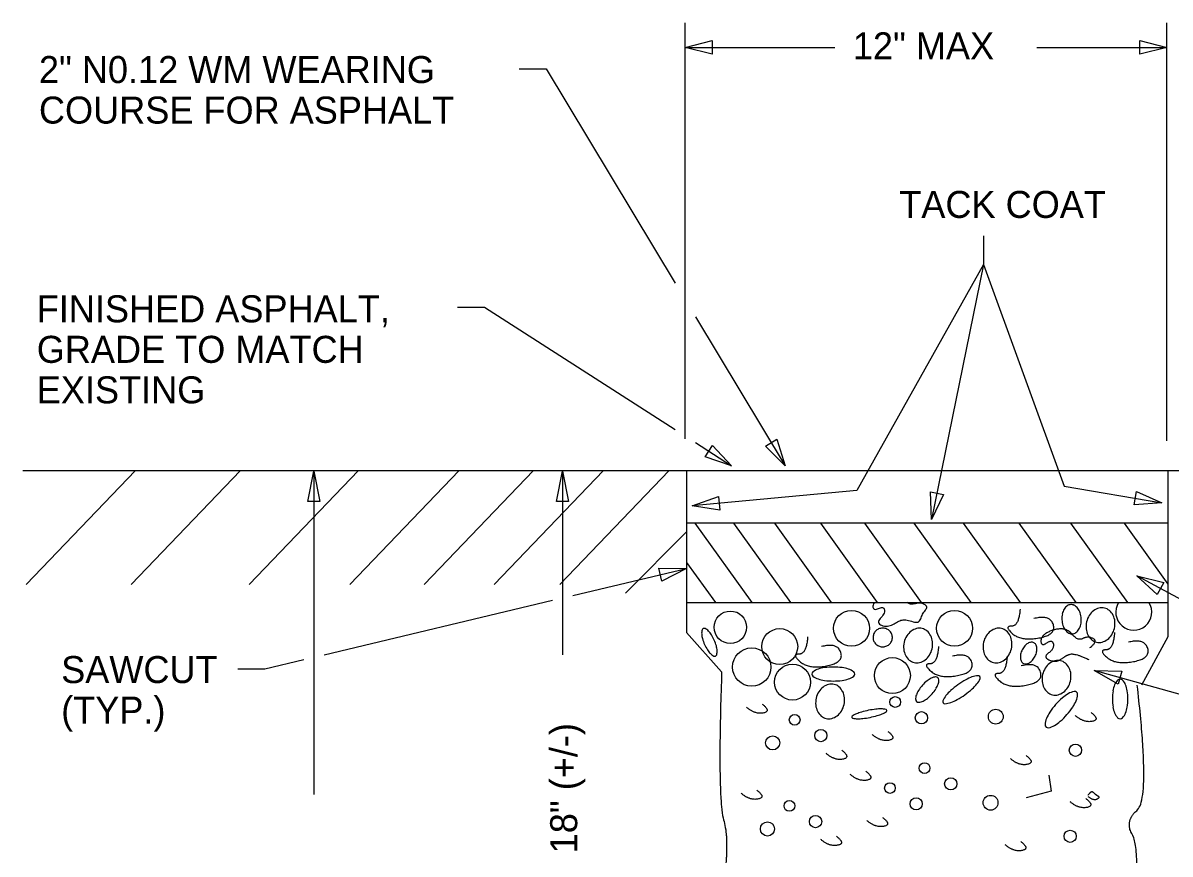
# Model space of a CAD drawing. Extents: x 10310.4 to 10401.1, y 10100.5 to 10143.6.
# Drawn here: x 10310.38 to 10338.7, y 10122.98 to 10143.48 of the extents above; entities that cross this region are included whole.
import ezdxf

# ---------------------------------------------------------------- set-up
doc = ezdxf.new("R2010")
doc.units = 0
for name, color, linetype in [('G-ANNO-TEXT', 7, 'Continuous'), ('G-DETL-LINE', 7, 'Continuous'), ('G-DETL-PATT', 7, 'Continuous')]:
    doc.layers.add(name, color=color, linetype=linetype)

msp = doc.modelspace()

# ---------------------------------------------------------------- linework, layer by layer
at = {"layer": 'G-ANNO-TEXT'}
for p, q in [((10326.732, 10133.217), (10326.732, 10143.483)), ((10338.624, 10133.174), (10338.624, 10143.483)), ((10326.732, 10142.88), (10330.423, 10142.88)), ((10335.408, 10142.88), (10338.624, 10142.88)), ((10322.63, 10142.355), (10323.297, 10142.355)), ((10323.297, 10142.355), (10326.482, 10137.063)), ((10334.093, 10137.519), (10332.813, 10131.227)), ((10321.107, 10136.471), (10321.774, 10136.471)), ((10321.774, 10136.471), (10326.482, 10133.448)), ((10326.982, 10136.232), (10329.195, 10132.554)), ((10326.982, 10133.127), (10327.873, 10132.554)), ((10317.561, 10132.423), (10317.561, 10124.448)), ((10323.701, 10132.426), (10323.701, 10127.888)), ((10323.951, 10129.355), (10326.765, 10130.024)), ((10341.376, 10127.947), (10337.879, 10129.844)), ((10317.811, 10127.895), (10323.451, 10129.236)), ((10315.684, 10127.548), (10316.35, 10127.548)), ((10316.35, 10127.548), (10317.311, 10127.776)), ((10341.293, 10126.261), (10336.825, 10127.508))]:
    msp.add_line(p, q, dxfattribs=at)
for points in [[(10327.398, 10142.714), (10326.732, 10142.88), (10327.398, 10143.047)], [(10337.957, 10143.047), (10338.624, 10142.88), (10337.957, 10142.714)], [(10328.994, 10133.212), (10329.195, 10132.554), (10328.709, 10133.04)], [(10327.402, 10133.055), (10327.873, 10132.554), (10327.222, 10132.774)], [(10317.411, 10131.673), (10317.561, 10132.423), (10317.711, 10131.673)], [(10323.551, 10131.676), (10323.701, 10132.426), (10323.851, 10131.676)], [(10327.582, 10131.462), (10326.903, 10131.567), (10327.551, 10131.794)], [(10333.11, 10131.848), (10332.813, 10131.227), (10332.783, 10131.914)], [(10337.869, 10131.919), (10338.498, 10131.642), (10337.813, 10131.591)], [(10326.078, 10130.032), (10326.765, 10130.024), (10326.155, 10129.708)], [(10338.385, 10129.38), (10337.879, 10129.844), (10338.544, 10129.673)], [(10337.422, 10127.169), (10336.825, 10127.508), (10337.512, 10127.49)]]:
    msp.add_lwpolyline(points, close=True, dxfattribs=at)
for points in [[(10334.093, 10138.234), (10334.093, 10137.519), (10330.969, 10131.943), (10326.903, 10131.567)], [(10334.093, 10137.519), (10336.089, 10132.056), (10338.498, 10131.642)]]:
    msp.add_lwpolyline(points, dxfattribs=at)
at = {"layer": 'G-DETL-LINE'}
for p, q in [((10310.377, 10132.442), (10354.529, 10132.442)), ((10326.765, 10132.442), (10326.765, 10131.144)), ((10338.647, 10132.442), (10338.647, 10129.182)), ((10326.765, 10131.144), (10326.757, 10129.182)), ((10338.647, 10131.144), (10326.757, 10131.144)), ((10326.757, 10129.182), (10338.647, 10129.182)), ((10326.765, 10129.182), (10326.765, 10128.442)), ((10338.647, 10129.182), (10338.647, 10128.334)), ((10326.765, 10128.442), (10327.629, 10127.469)), ((10338.647, 10128.334), (10337.999, 10127.143))]:
    msp.add_line(p, q, dxfattribs=at)
msp.add_open_spline([(10327.629, 10127.469), (10327.521, 10124.332), (10327.845, 10123.251), (10327.413, 10120.548), (10328.061, 10118.17), (10327.953, 10116.764), (10328.493, 10115.899), (10327.737, 10114.386), (10328.277, 10110.818), (10331.41, 10111.359), (10333.786, 10110.385), (10335.622, 10111.359), (10337.135, 10111.683), (10337.999, 10113.845), (10337.459, 10118.278), (10337.999, 10123.035), (10337.567, 10123.792), (10338.215, 10124.332), (10337.891, 10127.143)], degree=2, dxfattribs=at)
at = {"layer": 'G-DETL-PATT'}
for p, q in [((10313.155, 10132.441), (10310.454, 10129.63)), ((10315.747, 10132.441), (10313.046, 10129.63)), ((10318.663, 10132.441), (10315.963, 10129.63)), ((10321.148, 10132.441), (10318.447, 10129.63)), ((10322.984, 10132.441), (10320.284, 10129.63)), ((10324.712, 10132.441), (10322.012, 10129.63)), ((10326.333, 10132.441), (10323.632, 10129.63)), ((10326.969, 10131.144), (10328.373, 10129.182)), ((10327.923, 10131.144), (10329.327, 10129.182)), ((10328.93, 10131.144), (10330.334, 10129.182)), ((10330.069, 10131.144), (10331.473, 10129.182)), ((10331.155, 10131.144), (10332.559, 10129.182)), ((10332.374, 10131.144), (10333.778, 10129.182)), ((10333.593, 10131.144), (10334.997, 10129.182)), ((10334.97, 10131.144), (10336.374, 10129.182)), ((10336.242, 10131.144), (10337.646, 10129.182)), ((10337.567, 10131.144), (10338.647, 10129.634)), ((10326.765, 10130.927), (10325.253, 10129.414)), ((10326.765, 10130.171), (10327.473, 10129.182)), ((10335.709, 10124.921), (10335.765, 10124.527)), ((10335.765, 10124.527), (10335.147, 10124.359))]:
    msp.add_line(p, q, dxfattribs=at)
for points in [[(10331.4, 10129.182), (10331.394, 10129.173), (10331.38, 10129.146), (10331.37, 10129.119), (10331.366, 10129.094), (10331.366, 10129.07), (10331.37, 10129.049), (10331.378, 10129.032), (10331.391, 10129.02), (10331.407, 10129.014), (10331.427, 10129.013), (10331.45, 10129.018), (10331.474, 10129.026), (10331.5, 10129.036), (10331.526, 10129.045), (10331.552, 10129.053), (10331.575, 10129.058), (10331.597, 10129.058), (10331.615, 10129.051), (10331.63, 10129.039), (10331.64, 10129.022), (10331.647, 10129.001), (10331.649, 10128.977), (10331.647, 10128.95), (10331.64, 10128.922), (10331.628, 10128.894), (10331.61, 10128.866), (10331.59, 10128.839), (10331.567, 10128.812), (10331.545, 10128.786), (10331.526, 10128.761), (10331.51, 10128.736), (10331.501, 10128.713), (10331.5, 10128.691), (10331.508, 10128.67), (10331.524, 10128.651), (10331.548, 10128.634), (10331.577, 10128.62), (10331.61, 10128.608), (10331.646, 10128.601), (10331.683, 10128.597), (10331.72, 10128.598), (10331.756, 10128.604), (10331.79, 10128.613), (10331.823, 10128.626), (10331.855, 10128.642), (10331.885, 10128.658), (10331.915, 10128.676), (10331.944, 10128.693), (10331.972, 10128.709), (10332, 10128.722), (10332.028, 10128.734), (10332.056, 10128.743), (10332.085, 10128.75), (10332.114, 10128.754), (10332.145, 10128.755), (10332.177, 10128.753), (10332.211, 10128.748), (10332.246, 10128.74), (10332.283, 10128.73), (10332.32, 10128.719), (10332.357, 10128.709), (10332.392, 10128.701), (10332.425, 10128.695), (10332.454, 10128.695), (10332.48, 10128.7), (10332.501, 10128.711), (10332.518, 10128.729), (10332.532, 10128.751), (10332.543, 10128.777), (10332.554, 10128.805), (10332.565, 10128.835), (10332.577, 10128.865), (10332.59, 10128.894), (10332.606, 10128.921), (10332.624, 10128.947), (10332.642, 10128.97), (10332.659, 10128.993), (10332.674, 10129.014), (10332.685, 10129.033), (10332.692, 10129.053), (10332.692, 10129.071)], [(10332.692, 10129.071), (10332.685, 10129.089), (10332.672, 10129.106), (10332.653, 10129.122), (10332.63, 10129.136), (10332.603, 10129.147), (10332.573, 10129.156), (10332.542, 10129.162), (10332.511, 10129.164), (10332.48, 10129.162), (10332.449, 10129.157), (10332.418, 10129.152), (10332.387, 10129.146), (10332.357, 10129.141), (10332.326, 10129.14), (10332.295, 10129.142), (10332.264, 10129.151), (10332.232, 10129.166), (10332.206, 10129.182)]]:
    msp.add_lwpolyline(points, dxfattribs=at)
for centre, radius in [((10327.844, 10128.571), 0.401), ((10330.837, 10128.545), 0.444), ((10333.381, 10128.545), 0.444), ((10329.062, 10128.094), 0.444), ((10328.373, 10127.59), 0.474), ((10329.38, 10127.219), 0.444), ((10331.844, 10127.378), 0.444), ((10331.915, 10126.727), 0.132), ((10329.432, 10126.287), 0.132), ((10332.561, 10126.339), 0.151), ((10334.398, 10126.365), 0.183), ((10328.889, 10125.718), 0.174), ((10330.078, 10125.899), 0.151), ((10336.364, 10125.536), 0.151), ((10332.639, 10125.096), 0.132), ((10331.785, 10124.604), 0.132), ((10333.286, 10124.708), 0.151), ((10329.302, 10124.163), 0.132), ((10332.432, 10124.215), 0.151), ((10334.268, 10124.241), 0.183), ((10329.948, 10123.775), 0.151), ((10328.759, 10123.594), 0.174), ((10336.234, 10123.413), 0.151)]:
    msp.add_circle(centre, radius, dxfattribs=at)
for centre, radius, start, end in [((10336.422, 10128.821), 0.39, 149.7707, 167.9003), ((10336.323, 10128.878), 0.275, 125.3075, 149.7707), ((10336.257, 10128.971), 0.161, 93.1837, 125.3075), ((10336.257, 10128.971), 0.161, 61.0599, 93.1837), ((10336.202, 10128.872), 0.275, 36.5967, 61.0599), ((10336.11, 10128.803), 0.39, 18.4671, 36.5967), ((10337.076, 10128.633), 0.436, 127.6669, 148.2475), ((10337.033, 10128.687), 0.367, 103.8137, 127.6669), ((10337.015, 10128.761), 0.292, 76.9901, 103.8137), ((10337.015, 10128.761), 0.292, 50.1666, 76.9901), ((10336.967, 10128.703), 0.367, 26.3134, 50.1666), ((10337.805, 10128.943), 0.444, 147.4871, 32.5129), ((10336.576, 10128.788), 0.547, 167.9002, 183.1837), ((10336.576, 10128.788), 0.547, 183.1837, 198.4671), ((10335.961, 10128.753), 0.547, 3.1837, 18.4671), ((10335.961, 10128.753), 0.547, 347.9003, 3.1837), ((10337.151, 10128.586), 0.525, 166.9901, 185.7327), ((10337.151, 10128.586), 0.525, 148.2475, 166.9901), ((10336.905, 10128.672), 0.436, 5.7327, 26.3134), ((10336.816, 10128.663), 0.525, 346.9901, 5.7327), ((10327.42, 10128.425), 0.285, 163.6744, 184.6242), ((10327.724, 10128.45), 0.59, 184.6242, 195.7056), ((10327.198, 10128.491), 0.0534, 113.9883, 163.6744), ((10327.198, 10128.491), 0.0534, 64.3023, 113.9883), ((10327.097, 10128.282), 0.285, 43.3524, 64.3023), ((10326.876, 10128.073), 0.59, 32.271, 43.3524), ((10331.591, 10128.32), 0.224, 153.6698, 176.8163), ((10331.598, 10128.317), 0.232, 130.9122, 153.6698), ((10331.602, 10128.312), 0.238, 108.684, 130.9122), ((10331.605, 10128.305), 0.246, 86.8163, 108.684), ((10331.605, 10128.305), 0.246, 64.9486, 86.8163), ((10331.608, 10128.312), 0.238, 42.7204, 64.9486), ((10331.613, 10128.316), 0.232, 19.9629, 42.7204), ((10331.62, 10128.319), 0.224, 356.8163, 19.9629), ((10332.572, 10128.129), 0.436, 127.6669, 148.2475), ((10332.53, 10128.183), 0.367, 103.8137, 127.6669), ((10332.511, 10128.257), 0.292, 76.9901, 103.8137), ((10332.511, 10128.257), 0.292, 50.1666, 76.9901), ((10332.463, 10128.199), 0.367, 26.3134, 50.1666), ((10334.532, 10128.129), 0.436, 127.6669, 148.2475), ((10334.49, 10128.183), 0.367, 103.8137, 127.6669), ((10334.472, 10128.257), 0.292, 76.9901, 103.8137), ((10334.472, 10128.257), 0.292, 50.1666, 76.9901), ((10334.423, 10128.199), 0.367, 26.3134, 50.1666), ((10336.427, 10128.738), 0.39, 198.4671, 216.5967), ((10336.335, 10128.669), 0.275, 216.5967, 241.0599), ((10336.28, 10128.57), 0.161, 241.0599, 273.1837), ((10336.28, 10128.57), 0.161, 273.1837, 305.3075), ((10336.214, 10128.663), 0.275, 305.3075, 329.7707), ((10336.115, 10128.72), 0.39, 329.7707, 347.9003), ((10337.063, 10128.577), 0.436, 185.7327, 206.3134), ((10336.816, 10128.663), 0.525, 328.2475, 346.9901), ((10328.171, 10128.576), 1.055, 195.7056, 203.9883), ((10328.171, 10128.576), 1.055, 203.9883, 212.271), ((10326.483, 10127.824), 1.055, 23.9883, 32.271), ((10326.483, 10127.824), 1.055, 15.7056, 23.9883), ((10326.93, 10127.95), 0.59, 4.6242, 15.7056), ((10331.591, 10128.32), 0.224, 176.8163, 199.9629), ((10331.598, 10128.323), 0.232, 199.9629, 222.7204), ((10331.603, 10128.327), 0.238, 222.7204, 244.9486), ((10331.606, 10128.334), 0.246, 244.9486, 266.8163), ((10331.609, 10128.327), 0.238, 288.684, 310.9122), ((10331.613, 10128.322), 0.232, 310.9122, 333.6698), ((10331.62, 10128.319), 0.224, 333.6698, 356.8163), ((10332.647, 10128.082), 0.525, 166.9901, 185.7327), ((10332.647, 10128.082), 0.525, 148.2475, 166.9901), ((10332.401, 10128.168), 0.436, 5.7327, 26.3134), ((10332.313, 10128.159), 0.525, 346.9901, 5.7327), ((10334.608, 10128.082), 0.525, 166.9901, 185.7327), ((10334.608, 10128.082), 0.525, 148.2475, 166.9901), ((10334.361, 10128.168), 0.436, 5.7327, 26.3134), ((10334.273, 10128.159), 0.525, 346.9901, 5.7327), ((10335.462, 10127.808), 0.461, 139.002, 153.4071), ((10335.353, 10127.903), 0.317, 121.6044, 139.002), ((10335.299, 10127.991), 0.213, 97.1495, 121.6044), ((10335.286, 10128.09), 0.113, 63.4071, 97.1495), ((10335.286, 10128.09), 0.113, 29.6647, 63.4071), ((10335.2, 10128.041), 0.213, 5.2099, 29.6647), ((10337.001, 10128.546), 0.367, 206.3134, 230.1666), ((10336.952, 10128.488), 0.292, 230.1666, 256.9901), ((10336.952, 10128.488), 0.292, 256.9901, 283.8137), ((10336.934, 10128.562), 0.367, 283.8137, 307.6669), ((10336.892, 10128.616), 0.436, 307.6669, 328.2475), ((10327.778, 10128.328), 0.59, 212.271, 223.3524), ((10327.557, 10128.118), 0.285, 223.3524, 244.3023), ((10327.456, 10127.91), 0.0534, 244.3023, 293.9883), ((10327.456, 10127.91), 0.0534, 293.9883, 343.6744), ((10327.234, 10127.975), 0.285, 343.6744, 4.6242), ((10331.606, 10128.334), 0.246, 266.8163, 288.684), ((10332.559, 10128.073), 0.436, 185.7327, 206.3134), ((10332.497, 10128.042), 0.367, 206.3134, 230.1666), ((10332.388, 10128.112), 0.436, 307.6669, 328.2475), ((10332.313, 10128.159), 0.525, 328.2475, 346.9901), ((10334.519, 10128.073), 0.436, 185.7327, 206.3134), ((10334.457, 10128.042), 0.367, 206.3134, 230.1666), ((10334.349, 10128.112), 0.436, 307.6669, 328.2475), ((10334.273, 10128.159), 0.525, 328.2475, 346.9901), ((10335.321, 10127.839), 0.317, 167.8122, 185.2099), ((10335.462, 10127.808), 0.461, 153.4071, 167.8122), ((10334.956, 10128.062), 0.461, 319.002, 333.4071), ((10334.956, 10128.062), 0.461, 333.4071, 347.8122), ((10335.097, 10128.031), 0.317, 347.8122, 5.2099), ((10330.289, 10126.689), 0.895, 97.6808, 108.0348), ((10330.387, 10125.966), 1.624, 90, 97.6808), ((10330.387, 10125.966), 1.624, 82.3192, 90), ((10330.484, 10126.689), 0.895, 71.9652, 82.3192), ((10332.448, 10127.984), 0.292, 230.1666, 256.9901), ((10332.448, 10127.984), 0.292, 256.9901, 283.8137), ((10332.43, 10128.058), 0.367, 283.8137, 307.6669), ((10334.409, 10127.984), 0.292, 230.1666, 256.9901), ((10334.409, 10127.984), 0.292, 256.9901, 283.8137), ((10334.391, 10128.058), 0.367, 283.8137, 307.6669), ((10335.218, 10127.829), 0.213, 185.2099, 209.6647), ((10335.131, 10127.78), 0.113, 209.6647, 243.4071), ((10335.131, 10127.78), 0.113, 243.4071, 277.1495), ((10335.119, 10127.879), 0.213, 277.1495, 301.6044), ((10335.064, 10127.967), 0.317, 301.6044, 319.002), ((10336.065, 10127.286), 0.525, 148.2475, 166.9901), ((10335.989, 10127.333), 0.436, 127.6669, 148.2475), ((10335.947, 10127.388), 0.367, 103.8137, 127.6669), ((10335.929, 10127.461), 0.292, 76.9901, 103.8137), ((10335.929, 10127.461), 0.292, 50.1666, 76.9901), ((10335.881, 10127.403), 0.367, 26.3134, 50.1666), ((10335.819, 10127.372), 0.436, 5.7327, 26.3134), ((10329.925, 10127.418), 0.0671, 128.169, 180), ((10329.925, 10127.418), 0.0671, 180, 231.831), ((10330.142, 10127.14), 0.42, 108.0348, 128.169), ((10330.142, 10127.695), 0.42, 231.831, 251.9652), ((10330.289, 10128.146), 0.895, 251.9652, 262.3192), ((10330.387, 10128.869), 1.624, 262.3192, 270), ((10330.387, 10128.869), 1.624, 270, 277.6808), ((10330.484, 10128.146), 0.895, 277.6808, 288.0348), ((10330.631, 10127.14), 0.42, 51.831, 71.9652), ((10330.631, 10127.695), 0.42, 288.0348, 308.169), ((10330.849, 10127.418), 0.0671, 0, 51.831), ((10330.849, 10127.418), 0.0671, 308.169, 0), ((10333.054, 10126.813), 0.56, 116.2463, 128.7912), ((10332.933, 10127.057), 0.289, 93.9222, 116.2463), ((10332.919, 10127.273), 0.0721, 48.3319, 93.9222), ((10332.919, 10127.273), 0.0721, 2.7417, 48.3319), ((10332.702, 10127.263), 0.289, 340.4175, 2.7417), ((10334.653, 10125.484), 2.05, 119.1115, 125.5124), ((10334.19, 10126.316), 1.097, 110.3582, 119.1115), ((10333.977, 10126.889), 0.486, 92.3336, 110.3582), ((10333.556, 10127.48), 0.486, 320.6665, 338.6911), ((10333.959, 10127.323), 0.0527, 35.5124, 92.3336), ((10333.959, 10127.323), 0.0527, 338.6911, 35.5124), ((10336.065, 10127.286), 0.525, 166.9901, 185.7327), ((10335.73, 10127.363), 0.525, 346.9901, 5.7327), ((10337.67, 10127.017), 0.363, 136.5425, 158.5705), ((10337.468, 10127.208), 0.0849, 90, 136.5425), ((10337.468, 10127.208), 0.0849, 43.4575, 90), ((10337.266, 10127.017), 0.363, 21.4295, 43.4575), ((10330.475, 10126.703), 0.525, 148.2475, 166.9901), ((10330.399, 10126.749), 0.436, 127.6669, 148.2475), ((10330.357, 10126.804), 0.367, 103.8137, 127.6669), ((10330.339, 10126.878), 0.292, 76.9901, 103.8137), ((10330.339, 10126.878), 0.292, 50.1666, 76.9901), ((10330.29, 10126.819), 0.367, 26.3134, 50.1666), ((10330.228, 10126.789), 0.436, 5.7327, 26.3134), ((10332.964, 10126.712), 0.56, 147.8727, 160.4176), ((10333.308, 10126.496), 0.967, 138.3319, 147.8727), ((10333.308, 10126.496), 0.967, 128.7912, 138.3319), ((10332.102, 10127.57), 0.967, 318.3319, 327.8727), ((10332.446, 10127.354), 0.56, 327.8727, 340.4176), ((10334.017, 10126.193), 1.097, 131.9132, 140.6665), ((10334.653, 10125.484), 2.05, 125.5124, 131.9132), ((10332.446, 10128.576), 2.05, 305.5124, 311.9132), ((10333.083, 10127.867), 1.097, 311.9132, 320.6665), ((10335.977, 10127.277), 0.436, 185.7327, 206.3134), ((10335.915, 10127.247), 0.367, 206.3134, 230.1666), ((10335.806, 10127.317), 0.436, 307.6669, 328.2475), ((10335.73, 10127.363), 0.525, 328.2475, 346.9901), ((10336.416, 10126.541), 0.454, 100.6513, 120.7726), ((10336.345, 10126.916), 0.0724, 48.7876, 100.6513), ((10338.522, 10126.803), 1.246, 170.7659, 180), ((10337.998, 10126.888), 0.716, 158.5705, 170.7659), ((10336.938, 10126.888), 0.716, 9.2341, 21.4295), ((10336.414, 10126.803), 1.246, 0, 9.2341), ((10330.475, 10126.703), 0.525, 166.9901, 185.7327), ((10330.14, 10126.78), 0.525, 346.9901, 5.7327), ((10332.708, 10126.803), 0.289, 160.4175, 182.7417), ((10332.492, 10126.793), 0.0721, 182.7417, 228.3319), ((10332.492, 10126.793), 0.0721, 228.3319, 273.9222), ((10332.477, 10127.009), 0.289, 273.9222, 296.2463), ((10332.357, 10127.253), 0.56, 296.2463, 308.7912), ((10332.102, 10127.57), 0.967, 308.7912, 318.3319), ((10333.14, 10126.738), 0.0527, 158.6911, 215.5124), ((10333.544, 10126.58), 0.486, 140.6665, 158.6911), ((10333.14, 10126.738), 0.0527, 215.5124, 272.3336), ((10333.122, 10127.171), 0.486, 272.3336, 290.3582), ((10332.91, 10127.744), 1.097, 290.3582, 299.1115), ((10332.446, 10128.576), 2.05, 299.1115, 305.5124), ((10335.866, 10127.188), 0.292, 230.1666, 256.9901), ((10335.866, 10127.188), 0.292, 256.9901, 283.8137), ((10337.197, 10125.506), 1.756, 131.1157, 138.7876), ((10335.848, 10127.262), 0.367, 283.8137, 307.6669), ((10336.678, 10126.1), 0.967, 120.7726, 131.1157), ((10335.492, 10127.139), 0.967, 326.4594, 336.8025), ((10335.964, 10126.936), 0.454, 336.8025, 356.9238), ((10336.345, 10126.916), 0.0724, 356.9238, 48.7876), ((10338.522, 10126.803), 1.246, 180, 189.2341), ((10336.414, 10126.803), 1.246, 350.7659, 0), ((10330.386, 10126.694), 0.436, 185.7327, 206.3134), ((10330.324, 10126.663), 0.367, 206.3134, 230.1666), ((10330.216, 10126.733), 0.436, 307.6669, 328.2475), ((10330.14, 10126.78), 0.525, 328.2475, 346.9901), ((10331.141, 10126.001), 0.472, 112.7575, 127.3735), ((10331.395, 10125.395), 1.128, 106.0987, 112.7575), ((10331.684, 10124.393), 2.171, 101.2996, 106.0987), ((10331.684, 10124.393), 2.171, 96.5006, 101.2996), ((10331.566, 10125.429), 1.128, 89.8417, 96.5006), ((10331.157, 10127.475), 1.128, 286.0987, 292.7575), ((10331.568, 10126.086), 0.472, 75.2257, 89.8417), ((10331.411, 10126.869), 0.472, 292.7575, 307.3735), ((10331.681, 10126.516), 0.0273, 11.2996, 75.2257), ((10331.681, 10126.516), 0.0273, 307.3735, 11.2996), ((10336.54, 10125.941), 0.967, 146.4594, 156.8025), ((10337.197, 10125.506), 1.756, 138.7876, 146.4595), ((10334.835, 10127.574), 1.756, 311.1157, 318.7876), ((10334.835, 10127.574), 1.756, 318.7876, 326.4595), ((10337.998, 10126.717), 0.716, 189.2341, 201.4295), ((10337.67, 10126.589), 0.363, 201.4295, 223.4575), ((10337.266, 10126.589), 0.363, 316.5425, 338.5705), ((10336.938, 10126.717), 0.716, 338.5705, 350.7659), ((10330.276, 10126.605), 0.292, 230.1666, 256.9901), ((10330.276, 10126.605), 0.292, 256.9901, 283.8137), ((10330.258, 10126.678), 0.367, 283.8137, 307.6669), ((10330.871, 10126.354), 0.0273, 127.3735, 191.2996), ((10330.871, 10126.354), 0.0273, 191.2996, 255.2257), ((10330.984, 10126.784), 0.472, 255.2257, 269.8417), ((10330.986, 10127.441), 1.128, 269.8417, 276.5006), ((10330.868, 10128.477), 2.171, 276.5006, 281.2996), ((10330.868, 10128.477), 2.171, 281.2996, 286.0987), ((10335.687, 10126.164), 0.0724, 176.9238, 228.7876), ((10336.067, 10126.144), 0.454, 156.8025, 176.9238), ((10335.616, 10126.539), 0.454, 280.6513, 300.7726), ((10335.354, 10126.98), 0.967, 300.7726, 311.1157), ((10337.468, 10126.397), 0.0849, 223.4575, 270), ((10337.468, 10126.397), 0.0849, 270, 316.5425), ((10335.687, 10126.164), 0.0724, 228.7876, 280.6513)]:
    msp.add_arc(centre, radius, start, end, dxfattribs=at)
for points in [[(10334.997, 10129.022), (10334.97, 10128.598), (10334.599, 10128.598), (10335.023, 10128.227), (10335.898, 10128.386), (10335.739, 10128.89), (10335.341, 10128.784)], [(10336.719, 10128.068), (10336.931, 10128.227), (10336.666, 10128.359), (10336.427, 10128.227), (10336.162, 10128.545), (10335.792, 10128.518), (10335.5, 10128.333), (10335.527, 10128.094), (10335.792, 10128.28), (10335.845, 10128.041), (10335.553, 10127.829), (10335.898, 10127.696), (10336.136, 10127.882), (10336.348, 10127.935), (10336.692, 10127.776)], [(10337.328, 10128.439), (10337.302, 10128.014), (10336.931, 10128.014), (10337.355, 10127.643), (10338.229, 10127.802), (10338.07, 10128.306), (10337.673, 10128.2)], [(10329.751, 10128.333), (10329.725, 10127.908), (10329.354, 10127.908), (10329.778, 10127.537), (10330.652, 10127.696), (10330.493, 10128.2), (10330.096, 10128.094)], [(10332.983, 10128.094), (10332.957, 10127.67), (10332.586, 10127.67), (10333.01, 10127.298), (10333.884, 10127.457), (10333.725, 10127.961), (10333.328, 10127.855)], [(10334.679, 10127.855), (10334.652, 10127.431), (10334.281, 10127.431), (10334.705, 10127.06), (10335.58, 10127.219), (10335.421, 10127.723), (10335.023, 10127.617)], [(10328.63, 10126.676), (10328.863, 10126.494), (10328.449, 10126.417), (10328.242, 10126.598)], [(10336.752, 10126.468), (10336.984, 10126.287), (10336.571, 10126.21), (10336.364, 10126.391)], [(10331.734, 10126.002), (10331.967, 10125.821), (10331.553, 10125.744), (10331.346, 10125.925)], [(10330.596, 10125.536), (10330.828, 10125.355), (10330.415, 10125.278), (10330.208, 10125.459)], [(10335.148, 10125.407), (10335.381, 10125.226), (10334.967, 10125.148), (10334.76, 10125.329)], [(10331.191, 10125.019), (10331.423, 10124.837), (10331.01, 10124.76), (10330.803, 10124.941)], [(10328.5, 10124.552), (10328.733, 10124.371), (10328.319, 10124.293), (10328.112, 10124.474)], [(10336.674, 10124.397), (10336.803, 10124.294), (10336.984, 10124.371), (10336.881, 10124.423), (10336.752, 10124.553), (10336.674, 10124.423)], [(10336.622, 10124.345), (10336.854, 10124.163), (10336.441, 10124.086), (10336.234, 10124.267)], [(10331.604, 10123.879), (10331.837, 10123.697), (10331.423, 10123.62), (10331.216, 10123.801)], [(10330.466, 10123.413), (10330.699, 10123.231), (10330.285, 10123.154), (10330.078, 10123.335)], [(10335.018, 10123.283), (10335.251, 10123.102), (10334.837, 10123.024), (10334.63, 10123.205)]]:
    msp.add_open_spline(points, degree=2, dxfattribs=at)

# ---------------------------------------------------------------- texts
at = {"layer": 'G-ANNO-TEXT'}
for s, height, p in [('12" MAX', 0.6667, (10330.869, 10142.585)), ('2" N0.12 WM WEARING', 0.66667, (10310.772, 10142)), ('COURSE FOR ASPHALT', 0.66667, (10310.772, 10141)), ('TACK COAT', 0.6667, (10332.015, 10138.672)), ('FINISHED ASPHALT,', 0.66667, (10310.718, 10136.096)), ('GRADE TO MATCH', 0.66667, (10310.718, 10135.096)), ('EXISTING', 0.6667, (10310.718, 10134.096)), ('SAWCUT', 0.6667, (10311.321, 10127.194)), ('(TYP.)', 0.6667, (10311.321, 10126.194))]:
    msp.add_text(s, height=height, dxfattribs=at).set_placement(p)
msp.add_text('18" (+/-)', height=0.6667, rotation=90, dxfattribs=at).set_placement((10324.062, 10122.993))

doc.saveas('drawing.dxf')
